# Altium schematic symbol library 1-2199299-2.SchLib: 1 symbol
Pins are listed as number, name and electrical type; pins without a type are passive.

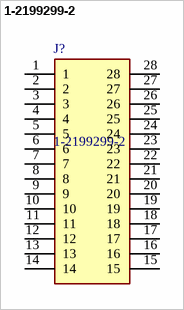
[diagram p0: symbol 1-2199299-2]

## 1-2199299-2
designator J?
TE CONNECTIVITY - 1-2199299-2 - IC SOCKET, DIP, 28POS, TH; Geometry.Height: 5.3mm
footprint DIPS1524W70P254L3556H530Q28N
pins: 1, 2, 3, 4, 5, 6, 7, 8, 9, 10, 11, 12, 13, 14, 15, 16, 17, 18, 19, 20, 21, 22, 23, 24, 25, 26, 27, 28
